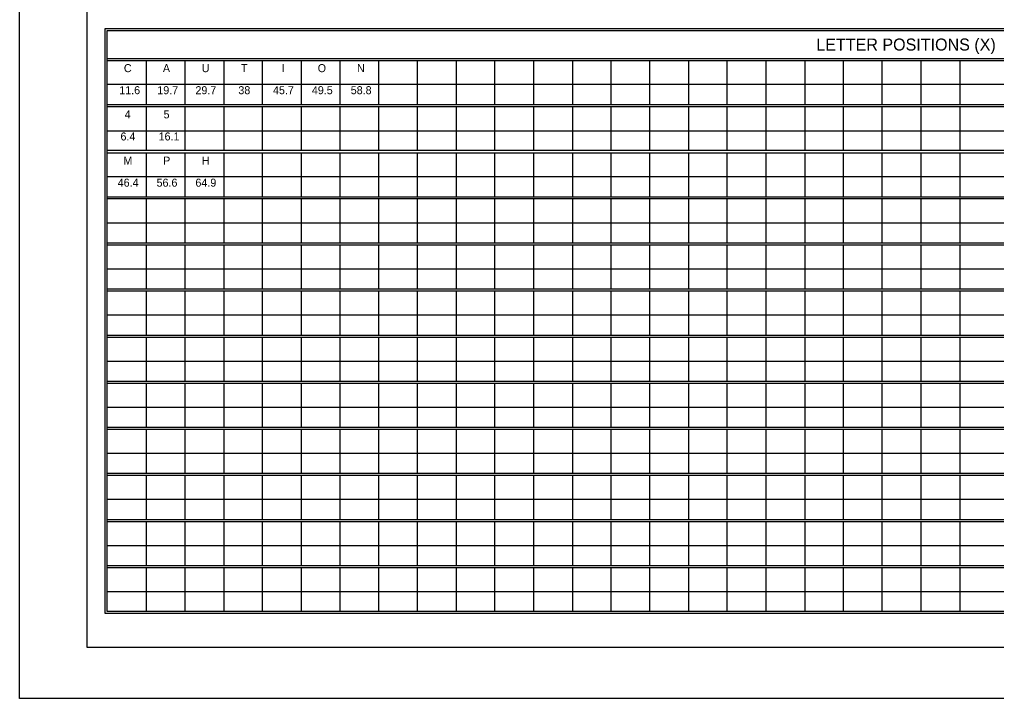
# Model space of a CAD drawing. Extents: x 1806251 to 1809821, y 414895 to 422886.
# Drawn here: x 1809672.13 to 1809679.34, y 415095.97 to 415100.98 of the extents above; entities that cross this region are included whole.
import ezdxf

# ---------------------------------------------------------------- set-up
doc = ezdxf.new("R2010")
doc.units = 0
doc.layers.add('GSSHT', color=7, linetype='Continuous')

msp = doc.modelspace()

# ---------------------------------------------------------------- linework, layer by layer
at = {"layer": 'GSSHT'}
for p, q in [((1809672.1349, 415095.9725), (1809672.1349, 415104.2262)), ((1809672.7816, 415100.6885), (1809684.4905, 415100.6885)), ((1809672.7816, 415100.6737), (1809684.4905, 415100.6737)), ((1809673.0681, 415100.6737), (1809673.0681, 415100.3489)), ((1809673.3545, 415100.6737), (1809673.3545, 415100.3489)), ((1809673.641, 415100.6737), (1809673.641, 415100.3489)), ((1809673.9245, 415100.6737), (1809673.9245, 415100.3489)), ((1809674.2109, 415100.6737), (1809674.2109, 415100.3489)), ((1809674.4973, 415100.6737), (1809674.4973, 415100.3489)), ((1809674.7808, 415100.6737), (1809674.7808, 415100.3489)), ((1809675.0673, 415100.6737), (1809675.0673, 415100.3489)), ((1809675.3537, 415100.6737), (1809675.3537, 415100.3489)), ((1809675.6372, 415100.6737), (1809675.6372, 415100.3489)), ((1809675.9237, 415100.6737), (1809675.9237, 415100.3489)), ((1809676.2101, 415100.6737), (1809676.2101, 415100.3489)), ((1809676.4936, 415100.6737), (1809676.4936, 415100.3489)), ((1809676.7801, 415100.6737), (1809676.7801, 415100.3489)), ((1809677.0665, 415100.6737), (1809677.0665, 415100.3489)), ((1809677.35, 415100.6737), (1809677.35, 415100.3489)), ((1809677.6364, 415100.6737), (1809677.6364, 415100.3489)), ((1809677.9229, 415100.6737), (1809677.9229, 415100.3489)), ((1809678.2064, 415100.6737), (1809678.2064, 415100.3489)), ((1809678.4928, 415100.6737), (1809678.4928, 415100.3489)), ((1809678.7793, 415100.6737), (1809678.7793, 415100.3489)), ((1809679.0657, 415100.6737), (1809679.0657, 415100.3489)), ((1809672.7816, 415100.4995), (1809683.6311, 415100.4995)), ((1809672.7816, 415100.3489), (1809684.4905, 415100.3489)), ((1809672.7816, 415100.3341), (1809684.4905, 415100.3341)), ((1809673.0681, 415100.3341), (1809673.0681, 415100.0122)), ((1809673.3545, 415100.3341), (1809673.3545, 415100.0122)), ((1809673.641, 415100.3341), (1809673.641, 415100.0122)), ((1809673.9245, 415100.3341), (1809673.9245, 415100.0122)), ((1809674.2109, 415100.3341), (1809674.2109, 415100.0122)), ((1809674.4973, 415100.3341), (1809674.4973, 415100.0122)), ((1809674.7808, 415100.3341), (1809674.7808, 415100.0122)), ((1809675.0673, 415100.3341), (1809675.0673, 415100.0122)), ((1809675.3537, 415100.3341), (1809675.3537, 415100.0122)), ((1809675.6372, 415100.3341), (1809675.6372, 415100.0122)), ((1809675.9237, 415100.3341), (1809675.9237, 415100.0122)), ((1809676.2101, 415100.3341), (1809676.2101, 415100.0122)), ((1809676.4936, 415100.3341), (1809676.4936, 415100.0122)), ((1809676.7801, 415100.3341), (1809676.7801, 415100.0122)), ((1809677.0665, 415100.3341), (1809677.0665, 415100.0122)), ((1809677.35, 415100.3341), (1809677.35, 415100.0122)), ((1809677.6364, 415100.3341), (1809677.6364, 415100.0122)), ((1809677.9229, 415100.3341), (1809677.9229, 415100.0122)), ((1809678.2064, 415100.3341), (1809678.2064, 415100.0122)), ((1809678.4928, 415100.3341), (1809678.4928, 415100.0122)), ((1809678.7793, 415100.3341), (1809678.7793, 415100.0122)), ((1809679.0657, 415100.3341), (1809679.0657, 415100.0122)), ((1809672.7816, 415100.1569), (1809683.6311, 415100.1569)), ((1809672.7816, 415100.0122), (1809684.4905, 415100.0122)), ((1809672.7816, 415099.9945), (1809684.4905, 415099.9945)), ((1809673.0681, 415099.9945), (1809673.0681, 415099.6697)), ((1809673.3545, 415099.9945), (1809673.3545, 415099.6697)), ((1809673.641, 415099.9945), (1809673.641, 415099.6697)), ((1809673.9245, 415099.9945), (1809673.9245, 415099.6697)), ((1809674.2109, 415099.9945), (1809674.2109, 415099.6697)), ((1809674.4973, 415099.9945), (1809674.4973, 415099.6697)), ((1809674.7808, 415099.9945), (1809674.7808, 415099.6697)), ((1809675.0673, 415099.9945), (1809675.0673, 415099.6697)), ((1809675.3537, 415099.9945), (1809675.3537, 415099.6697)), ((1809675.6372, 415099.9945), (1809675.6372, 415099.6697)), ((1809675.9237, 415099.9945), (1809675.9237, 415099.6697)), ((1809676.2101, 415099.9945), (1809676.2101, 415099.6697)), ((1809676.4936, 415099.9945), (1809676.4936, 415099.6697)), ((1809676.7801, 415099.9945), (1809676.7801, 415099.6697)), ((1809677.0665, 415099.9945), (1809677.0665, 415099.6697)), ((1809677.35, 415099.9945), (1809677.35, 415099.6697)), ((1809677.6364, 415099.9945), (1809677.6364, 415099.6697)), ((1809677.9229, 415099.9945), (1809677.9229, 415099.6697)), ((1809678.2064, 415099.9945), (1809678.2064, 415099.6697)), ((1809678.4928, 415099.9945), (1809678.4928, 415099.6697)), ((1809678.7793, 415099.9945), (1809678.7793, 415099.6697)), ((1809679.0657, 415099.9945), (1809679.0657, 415099.6697)), ((1809672.7816, 415099.8203), (1809683.6311, 415099.8203)), ((1809672.7816, 415099.6697), (1809684.4905, 415099.6697)), ((1809672.7816, 415099.6579), (1809684.4905, 415099.6579)), ((1809673.0681, 415099.6579), (1809673.0681, 415099.3301)), ((1809673.3545, 415099.6579), (1809673.3545, 415099.3301)), ((1809673.641, 415099.6579), (1809673.641, 415099.3301)), ((1809673.9245, 415099.6579), (1809673.9245, 415099.3301)), ((1809674.2109, 415099.6579), (1809674.2109, 415099.3301)), ((1809674.4973, 415099.6579), (1809674.4973, 415099.3301)), ((1809674.7808, 415099.6579), (1809674.7808, 415099.3301)), ((1809675.0673, 415099.6579), (1809675.0673, 415099.3301)), ((1809675.3537, 415099.6579), (1809675.3537, 415099.3301)), ((1809675.6372, 415099.6579), (1809675.6372, 415099.3301)), ((1809675.9237, 415099.6579), (1809675.9237, 415099.3301)), ((1809676.2101, 415099.6579), (1809676.2101, 415099.3301)), ((1809676.4936, 415099.6579), (1809676.4936, 415099.3301)), ((1809676.7801, 415099.6579), (1809676.7801, 415099.3301)), ((1809677.0665, 415099.6579), (1809677.0665, 415099.3301)), ((1809677.35, 415099.6579), (1809677.35, 415099.3301)), ((1809677.6364, 415099.6579), (1809677.6364, 415099.3301)), ((1809677.9229, 415099.6579), (1809677.9229, 415099.3301)), ((1809678.2064, 415099.6579), (1809678.2064, 415099.3301)), ((1809678.4928, 415099.6579), (1809678.4928, 415099.3301)), ((1809678.7793, 415099.6579), (1809678.7793, 415099.3301)), ((1809679.0657, 415099.6579), (1809679.0657, 415099.3301)), ((1809672.7816, 415099.4777), (1809683.6311, 415099.4777)), ((1809672.7816, 415099.3301), (1809684.4905, 415099.3301)), ((1809672.7816, 415099.3153), (1809684.4905, 415099.3153)), ((1809673.0681, 415099.3153), (1809673.0681, 415098.9905)), ((1809673.3545, 415099.3153), (1809673.3545, 415098.9905)), ((1809673.641, 415099.3153), (1809673.641, 415098.9905)), ((1809673.9245, 415099.3153), (1809673.9245, 415098.9905)), ((1809674.2109, 415099.3153), (1809674.2109, 415098.9905)), ((1809674.4973, 415099.3153), (1809674.4973, 415098.9905)), ((1809674.7808, 415099.3153), (1809674.7808, 415098.9905)), ((1809675.0673, 415099.3153), (1809675.0673, 415098.9905)), ((1809675.3537, 415099.3153), (1809675.3537, 415098.9905)), ((1809675.6372, 415099.3153), (1809675.6372, 415098.9905)), ((1809675.9237, 415099.3153), (1809675.9237, 415098.9905)), ((1809676.2101, 415099.3153), (1809676.2101, 415098.9905)), ((1809676.4936, 415099.3153), (1809676.4936, 415098.9905)), ((1809676.7801, 415099.3153), (1809676.7801, 415098.9905)), ((1809677.0665, 415099.3153), (1809677.0665, 415098.9905)), ((1809677.35, 415099.3153), (1809677.35, 415098.9905)), ((1809677.6364, 415099.3153), (1809677.6364, 415098.9905)), ((1809677.9229, 415099.3153), (1809677.9229, 415098.9905)), ((1809678.2064, 415099.3153), (1809678.2064, 415098.9905)), ((1809678.4928, 415099.3153), (1809678.4928, 415098.9905)), ((1809678.7793, 415099.3153), (1809678.7793, 415098.9905)), ((1809679.0657, 415099.3153), (1809679.0657, 415098.9905)), ((1809672.7816, 415099.1381), (1809683.6311, 415099.1381)), ((1809672.7816, 415098.9905), (1809684.4905, 415098.9905)), ((1809672.7816, 415098.9757), (1809684.4905, 415098.9757)), ((1809673.0681, 415098.9757), (1809673.0681, 415098.6509)), ((1809673.3545, 415098.9757), (1809673.3545, 415098.6509)), ((1809673.641, 415098.9757), (1809673.641, 415098.6509)), ((1809673.9245, 415098.9757), (1809673.9245, 415098.6509)), ((1809674.2109, 415098.9757), (1809674.2109, 415098.6509)), ((1809674.4973, 415098.9757), (1809674.4973, 415098.6509)), ((1809674.7808, 415098.9757), (1809674.7808, 415098.6509)), ((1809675.0673, 415098.9757), (1809675.0673, 415098.6509)), ((1809675.3537, 415098.9757), (1809675.3537, 415098.6509)), ((1809675.6372, 415098.9757), (1809675.6372, 415098.6509)), ((1809675.9237, 415098.9757), (1809675.9237, 415098.6509)), ((1809676.2101, 415098.9757), (1809676.2101, 415098.6509)), ((1809676.4936, 415098.9757), (1809676.4936, 415098.6509)), ((1809676.7801, 415098.9757), (1809676.7801, 415098.6509)), ((1809677.0665, 415098.9757), (1809677.0665, 415098.6509)), ((1809677.35, 415098.9757), (1809677.35, 415098.6509)), ((1809677.6364, 415098.9757), (1809677.6364, 415098.6509)), ((1809677.9229, 415098.9757), (1809677.9229, 415098.6509)), ((1809678.2064, 415098.9757), (1809678.2064, 415098.6509)), ((1809678.4928, 415098.9757), (1809678.4928, 415098.6509)), ((1809678.7793, 415098.9757), (1809678.7793, 415098.6509)), ((1809679.0657, 415098.9757), (1809679.0657, 415098.6509)), ((1809672.7816, 415098.7985), (1809683.6311, 415098.7985)), ((1809672.7816, 415098.6509), (1809684.4905, 415098.6509)), ((1809672.7816, 415098.6361), (1809684.4905, 415098.6361)), ((1809673.0681, 415098.6361), (1809673.0681, 415098.3113)), ((1809673.3545, 415098.6361), (1809673.3545, 415098.3113)), ((1809673.641, 415098.6361), (1809673.641, 415098.3113)), ((1809673.9245, 415098.6361), (1809673.9245, 415098.3113)), ((1809674.2109, 415098.6361), (1809674.2109, 415098.3113)), ((1809674.4973, 415098.6361), (1809674.4973, 415098.3113)), ((1809674.7808, 415098.6361), (1809674.7808, 415098.3113)), ((1809675.0673, 415098.6361), (1809675.0673, 415098.3113)), ((1809675.3537, 415098.6361), (1809675.3537, 415098.3113)), ((1809675.6372, 415098.6361), (1809675.6372, 415098.3113)), ((1809675.9237, 415098.6361), (1809675.9237, 415098.3113)), ((1809676.2101, 415098.6361), (1809676.2101, 415098.3113)), ((1809676.4936, 415098.6361), (1809676.4936, 415098.3113)), ((1809676.7801, 415098.6361), (1809676.7801, 415098.3113)), ((1809677.0665, 415098.6361), (1809677.0665, 415098.3113)), ((1809677.35, 415098.6361), (1809677.35, 415098.3113)), ((1809677.6364, 415098.6361), (1809677.6364, 415098.3113)), ((1809677.9229, 415098.6361), (1809677.9229, 415098.3113)), ((1809678.2064, 415098.6361), (1809678.2064, 415098.3113)), ((1809678.4928, 415098.6361), (1809678.4928, 415098.3113)), ((1809678.7793, 415098.6361), (1809678.7793, 415098.3113)), ((1809679.0657, 415098.6361), (1809679.0657, 415098.3113)), ((1809672.7816, 415098.4589), (1809683.6311, 415098.4589)), ((1809672.7816, 415098.3113), (1809684.4905, 415098.3113)), ((1809672.7816, 415098.2965), (1809684.4905, 415098.2965)), ((1809673.0681, 415098.2965), (1809673.0681, 415097.9717)), ((1809673.3545, 415098.2965), (1809673.3545, 415097.9717)), ((1809673.641, 415098.2965), (1809673.641, 415097.9717)), ((1809673.9245, 415098.2965), (1809673.9245, 415097.9717)), ((1809674.2109, 415098.2965), (1809674.2109, 415097.9717)), ((1809674.4973, 415098.2965), (1809674.4973, 415097.9717)), ((1809674.7808, 415098.2965), (1809674.7808, 415097.9717)), ((1809675.0673, 415098.2965), (1809675.0673, 415097.9717)), ((1809675.3537, 415098.2965), (1809675.3537, 415097.9717)), ((1809675.6372, 415098.2965), (1809675.6372, 415097.9717)), ((1809675.9237, 415098.2965), (1809675.9237, 415097.9717)), ((1809676.2101, 415098.2965), (1809676.2101, 415097.9717)), ((1809676.4936, 415098.2965), (1809676.4936, 415097.9717)), ((1809676.7801, 415098.2965), (1809676.7801, 415097.9717)), ((1809677.0665, 415098.2965), (1809677.0665, 415097.9717)), ((1809677.35, 415098.2965), (1809677.35, 415097.9717)), ((1809677.6364, 415098.2965), (1809677.6364, 415097.9717)), ((1809677.9229, 415098.2965), (1809677.9229, 415097.9717)), ((1809678.2064, 415098.2965), (1809678.2064, 415097.9717)), ((1809678.4928, 415098.2965), (1809678.4928, 415097.9717)), ((1809678.7793, 415098.2965), (1809678.7793, 415097.9717)), ((1809679.0657, 415098.2965), (1809679.0657, 415097.9717)), ((1809672.7816, 415098.1193), (1809683.6311, 415098.1193)), ((1809672.7816, 415097.9717), (1809684.4905, 415097.9717)), ((1809672.7816, 415097.9569), (1809684.4905, 415097.9569)), ((1809673.0681, 415097.9569), (1809673.0681, 415097.6321)), ((1809673.3545, 415097.9569), (1809673.3545, 415097.6321)), ((1809673.641, 415097.9569), (1809673.641, 415097.6321)), ((1809673.9245, 415097.9569), (1809673.9245, 415097.6321)), ((1809674.2109, 415097.9569), (1809674.2109, 415097.6321)), ((1809674.4973, 415097.9569), (1809674.4973, 415097.6321)), ((1809674.7808, 415097.9569), (1809674.7808, 415097.6321)), ((1809675.0673, 415097.9569), (1809675.0673, 415097.6321)), ((1809675.3537, 415097.9569), (1809675.3537, 415097.6321)), ((1809675.6372, 415097.9569), (1809675.6372, 415097.6321)), ((1809675.9237, 415097.9569), (1809675.9237, 415097.6321)), ((1809676.2101, 415097.9569), (1809676.2101, 415097.6321)), ((1809676.4936, 415097.9569), (1809676.4936, 415097.6321)), ((1809676.7801, 415097.9569), (1809676.7801, 415097.6321)), ((1809677.0665, 415097.9569), (1809677.0665, 415097.6321)), ((1809677.35, 415097.9569), (1809677.35, 415097.6321)), ((1809677.6364, 415097.9569), (1809677.6364, 415097.6321)), ((1809677.9229, 415097.9569), (1809677.9229, 415097.6321)), ((1809678.2064, 415097.9569), (1809678.2064, 415097.6321)), ((1809678.4928, 415097.9569), (1809678.4928, 415097.6321)), ((1809678.7793, 415097.9569), (1809678.7793, 415097.6321)), ((1809679.0657, 415097.9569), (1809679.0657, 415097.6321)), ((1809672.7816, 415097.7797), (1809683.6311, 415097.7797)), ((1809672.7816, 415097.6321), (1809684.4905, 415097.6321)), ((1809672.7816, 415097.6173), (1809684.4905, 415097.6173)), ((1809673.0681, 415097.6173), (1809673.0681, 415097.2925)), ((1809673.3545, 415097.6173), (1809673.3545, 415097.2925)), ((1809673.641, 415097.6173), (1809673.641, 415097.2925)), ((1809673.9245, 415097.6173), (1809673.9245, 415097.2925)), ((1809674.2109, 415097.6173), (1809674.2109, 415097.2925)), ((1809674.4973, 415097.6173), (1809674.4973, 415097.2925)), ((1809674.7808, 415097.6173), (1809674.7808, 415097.2925)), ((1809675.0673, 415097.6173), (1809675.0673, 415097.2925)), ((1809675.3537, 415097.6173), (1809675.3537, 415097.2925)), ((1809675.6372, 415097.6173), (1809675.6372, 415097.2925)), ((1809675.9237, 415097.6173), (1809675.9237, 415097.2925)), ((1809676.2101, 415097.6173), (1809676.2101, 415097.2925)), ((1809676.4936, 415097.6173), (1809676.4936, 415097.2925)), ((1809676.7801, 415097.6173), (1809676.7801, 415097.2925)), ((1809677.0665, 415097.6173), (1809677.0665, 415097.2925)), ((1809677.35, 415097.6173), (1809677.35, 415097.2925)), ((1809677.6364, 415097.6173), (1809677.6364, 415097.2925)), ((1809677.9229, 415097.6173), (1809677.9229, 415097.2925)), ((1809678.2064, 415097.6173), (1809678.2064, 415097.2925)), ((1809678.4928, 415097.6173), (1809678.4928, 415097.2925)), ((1809678.7793, 415097.6173), (1809678.7793, 415097.2925)), ((1809679.0657, 415097.6173), (1809679.0657, 415097.2925)), ((1809672.7816, 415097.4401), (1809683.6311, 415097.4401)), ((1809672.7816, 415097.2925), (1809684.4905, 415097.2925)), ((1809672.7816, 415097.2777), (1809684.4905, 415097.2777)), ((1809673.0681, 415097.2777), (1809673.0681, 415096.9529)), ((1809673.3545, 415097.2777), (1809673.3545, 415096.9529)), ((1809673.641, 415097.2777), (1809673.641, 415096.9529)), ((1809673.9245, 415097.2777), (1809673.9245, 415096.9529)), ((1809674.2109, 415097.2777), (1809674.2109, 415096.9529)), ((1809674.4973, 415097.2777), (1809674.4973, 415096.9529)), ((1809674.7808, 415097.2777), (1809674.7808, 415096.9529)), ((1809675.0673, 415097.2777), (1809675.0673, 415096.9529)), ((1809675.3537, 415097.2777), (1809675.3537, 415096.9529)), ((1809675.6372, 415097.2777), (1809675.6372, 415096.9529)), ((1809675.9237, 415097.2777), (1809675.9237, 415096.9529)), ((1809676.2101, 415097.2777), (1809676.2101, 415096.9529)), ((1809676.4936, 415097.2777), (1809676.4936, 415096.9529)), ((1809676.7801, 415097.2777), (1809676.7801, 415096.9529)), ((1809677.0665, 415097.2777), (1809677.0665, 415096.9529)), ((1809677.35, 415097.2777), (1809677.35, 415096.9529)), ((1809677.6364, 415097.2777), (1809677.6364, 415096.9529)), ((1809677.9229, 415097.2777), (1809677.9229, 415096.9529)), ((1809678.2064, 415097.2777), (1809678.2064, 415096.9529)), ((1809678.4928, 415097.2777), (1809678.4928, 415096.9529)), ((1809678.7793, 415097.2777), (1809678.7793, 415096.9529)), ((1809679.0657, 415097.2777), (1809679.0657, 415096.9529)), ((1809672.7816, 415097.1005), (1809683.6311, 415097.1005)), ((1809672.7816, 415096.9529), (1809684.4905, 415096.9529)), ((1809672.7816, 415096.9381), (1809684.4905, 415096.9381)), ((1809673.0681, 415096.9381), (1809673.0681, 415096.6133)), ((1809673.3545, 415096.9381), (1809673.3545, 415096.6133)), ((1809673.641, 415096.9381), (1809673.641, 415096.6133)), ((1809673.9245, 415096.9381), (1809673.9245, 415096.6133)), ((1809674.2109, 415096.9381), (1809674.2109, 415096.6133)), ((1809674.4973, 415096.9381), (1809674.4973, 415096.6133)), ((1809674.7808, 415096.9381), (1809674.7808, 415096.6133)), ((1809675.0673, 415096.9381), (1809675.0673, 415096.6133)), ((1809675.3537, 415096.9381), (1809675.3537, 415096.6133)), ((1809675.6372, 415096.9381), (1809675.6372, 415096.6133)), ((1809675.9237, 415096.9381), (1809675.9237, 415096.6133)), ((1809676.2101, 415096.9381), (1809676.2101, 415096.6133)), ((1809676.4936, 415096.9381), (1809676.4936, 415096.6133)), ((1809676.7801, 415096.9381), (1809676.7801, 415096.6133)), ((1809677.0665, 415096.9381), (1809677.0665, 415096.6133)), ((1809677.35, 415096.9381), (1809677.35, 415096.6133)), ((1809677.6364, 415096.9381), (1809677.6364, 415096.6133)), ((1809677.9229, 415096.9381), (1809677.9229, 415096.6133)), ((1809678.2064, 415096.9381), (1809678.2064, 415096.6133)), ((1809678.4928, 415096.9381), (1809678.4928, 415096.6133)), ((1809678.7793, 415096.9381), (1809678.7793, 415096.6133)), ((1809679.0657, 415096.9381), (1809679.0657, 415096.6133)), ((1809672.7816, 415096.7609), (1809683.6311, 415096.7609)), ((1809684.8891, 415095.9725), (1809672.1349, 415095.9725))]:
    msp.add_line(p, q, dxfattribs=at)
for points in [[(1809672.634, 415103.8512), (1809684.6381, 415103.8512), (1809684.6381, 415096.3475), (1809672.634, 415096.3475)], [(1809672.7669, 415100.91), (1809684.5052, 415100.91), (1809684.5052, 415096.5985), (1809672.7669, 415096.5985)], [(1809672.7816, 415100.8952), (1809684.4905, 415100.8952), (1809684.4905, 415096.6133), (1809672.7816, 415096.6133)]]:
    msp.add_lwpolyline(points, close=True, dxfattribs=at)

# ---------------------------------------------------------------- texts
for s, height, p in [('LETTER POSITIONS (X)', 0.088592, (1809678.0085, 415100.7475)), ('C', 0.059, (1809672.9041, 415100.5883)), ('A', 0.059, (1809673.1916, 415100.5883)), ('U', 0.059, (1809673.4781, 415100.5883)), ('T', 0.059, (1809673.7676, 415100.5883)), ('I', 0.059, (1809674.0681, 415100.5883)), ('O', 0.059, (1809674.3331, 415100.5883)), ('N', 0.059, (1809674.6231, 415100.5883)), ('11.6', 0.05903, (1809672.8701, 415100.4257)), ('19.7', 0.05903, (1809673.1506, 415100.4257)), ('29.7', 0.05903, (1809673.4316, 415100.4257)), ('38', 0.05903, (1809673.7481, 415100.4257)), ('45.7', 0.05903, (1809674.0036, 415100.4257)), ('49.5', 0.05903, (1809674.2901, 415100.4257)), ('58.8', 0.05903, (1809674.5766, 415100.4257)), ('4', 0.059, (1809672.9101, 415100.2476)), ('5', 0.059, (1809673.1966, 415100.2476)), ('6.4', 0.05903, (1809672.8791, 415100.0849)), ('16.1', 0.05903, (1809673.1601, 415100.0849)), ('M', 0.059, (1809672.9006, 415099.9068)), ('P', 0.059, (1809673.1936, 415099.9068)), ('H', 0.059, (1809673.4781, 415099.9068)), ('46.4', 0.05903, (1809672.8586, 415099.7442)), ('56.6', 0.05903, (1809673.1451, 415099.7442)), ('64.9', 0.05903, (1809673.4316, 415099.7442))]:
    msp.add_text(s, height=height, dxfattribs=at).set_placement(p)

doc.saveas('drawing.dxf')
